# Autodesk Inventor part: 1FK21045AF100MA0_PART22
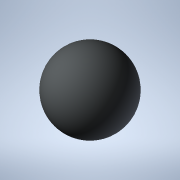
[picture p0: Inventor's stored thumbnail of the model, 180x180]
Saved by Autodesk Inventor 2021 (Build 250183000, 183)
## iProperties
Created: 2025-04
Part Number: 1FK21045AF100MA0_PART22
Material: Generic
Catalog Web Link: www.3dfindit.com
Description: -Servo synchronous motor
Document SubType Name: Modeling
Designer: psAdmin
Mass: 0.137258 g
Surface Area: 1.2868 cm^2
Volume: 0.137258 cm^3
Density: 1 g/cm^3
Appearance: PSOLRGB-212-217-219
Category: PARTsolutions
Title: 1FK21045AF100MA0_PART22
Author: Cadenas PARTsolutions
Comments: Servo synchronous motor
Sending System: PARTsolutions
Preprocessor: ST-DEVELOPER v19.3
PSOL_IDENT_0: {$CADENAS_DATA/23d-libs/siemens_ag/_cat_/52/6b/1fk21045af100ma0.prj},216 {VTYP=3D},{NB=1FK21045AF100
PSOL_IDENT_1: MA0_PART22},{LINA=1FK21045AF100MA0_PART22},{NN=1FK21045AF100MA0_PART22},{NOPRJ=TRUE},{DATE=19.08.202
PSOL_IDENT_2: 5 14:00:38},{GEOMDATE=30.07.2025 02:01:45},{VERSION=},{LINEID=10},{WBVAR=},{WBNUMERIC=}  {NB=1FK2104
PSOL_IDENT_3: 5AF100MA0_PART22},{LINA=1FK21045AF100MA0_PART22},{KT=DUMMY},{PREVIEW=../../../_pool_/cb/72/p_d211_xx
PSOL_IDENT_4: _00434j.png},{DESCSHORT=SIMOTICS S-1FK2 HD, SINAMICS S210 3AC 400V-480V, 2.4 Nm, 3000 rpm},{DESCLONG=
PSOL_IDENT_5: SIMOTICS S-1FK2 HD servo motor M0=2.4 Nm; PN = 0.75 kW at nN=3000 rpm (380-480 V); PN = 0.375 kW at
PSOL_IDENT_6: nN=1500 rpm (200-240 V); with holding brake; degree of protection IP64; cylindrical shaft D19x40mm;
PSOL_IDENT_7: absolute encoder 22-bit + 12-bit multiturn (encoder AM22DQC); with OCC interface; plug size M17, rot
PSOL_IDENT_8: atable; SIMOTICS S-1FK2 servomotorfor a wide range of uses in industrial environments. SIMOTICS S‑1F
PSOL_IDENT_9: K2 servomotors are compact synchronous motors with a high dynamic performance that set themselves ap
PSOL_IDENT_10: art as a result of their high power density, degree of protection and overload capability. The motor
PSOL_IDENT_11: s are available in two variants: as High Dynamic variant (highest dynamic performance as a result of
PSOL_IDENT_12: the low intrinsic moment of inertia for applications demanding a high dynamic performance with low
PSOL_IDENT_13: moved masses) - and as Compact variant (precise and stable closed-loop control for medium up to larg
PSOL_IDENT_14: e moved masses as a result of a medium intrinsic moment of inertia). SIMOTICSS‑1FK2 servomotors full
PSOL_IDENT_15: y exploit their strengths in a system with the SINAMICSS210 frequency converter and simple connectio
PSOL_IDENT_16: n using the one cable connection (OCC). Advantages include the short control and positioning times,
PSOL_IDENT_17: fast and precise correction of disturbing quantities as well as stable control with a high dynamic p
PSOL_IDENT_18: erformance. The servo motors can be configured to address a wide range of requirements. For example
PSOL_IDENT_19: with and without holding brake, IP64 or IP65 degree of protection, singleturn or multiturn absolute
PSOL_IDENT_20: encoders - to name just a few. Further, the servomotors are available in different shaft heights ext
PSOL_IDENT_21: ending from 20 to 100. A shaft sealing ring is available to achieve an IP65 degree of protection and
PSOL_IDENT_22: for subsequent mounting at the motor or as spare part. SIMOTICS - the optimum motor for each and ev
PSOL_IDENT_23: ery motion control application.},{INTNO=804766906411},{SUPPLIERALTNO=1FK2104-5AF10-0MA0},{MANUID=1FK
PSOL_IDENT_24: 21045AF100MA0},{MANUNAME=Siemens},{MANUTYPEDESC=Synchronous motor 1FK2-HD 2.4 NM},{AAU732=SIMOTICS},
PSOL_IDENT_25: {AAO057=S-1FK2},{AAU734=SIMOTICS S-1FK2 HD servo motor M0=2.4 Nm; PN = 0.75 kW at nN=3000 rpm (380-4
PSOL_IDENT_26: 80 V); PN = 0.375 kW at nN=1500 rpm (200-240 V); with holding brake; degree of protection IP64; cyli
PSOL_IDENT_27: ndrical shaft D19x40mm; absolute encoder 22-bit + 12-bit multiturn (encoder AM22DQC); with OCC inter
PSOL_IDENT_28: face; plug size M17, rotatable;},{AAW338=Synchronous motor 1FK2-HD 2.4 NM},{AAO742=SIMOTICS},{AAO663=
PSOL_IDENT_29: 4042948693070},{NOCUPEROU=1},{PRICEQUANTITY=1},{QUANTITYMIN=1},{QUANTITYINT=1},{CTN=85015100},{COO=D
PSOL_IDENT_30: E},{AAO676=1FK2104-5AF10-0MA0},{AAO677=Siemens AG},{ORDERUNIT=C62},{CONTENTUNIT=C62}
NB: 1FK21045AF100MA0_PART22
NT: Servo synchronous motor
NBSYN: $MANUID._PART22
LINA: 1FK21045AF100MA0_PART22
CATALOG: SIEMENS
PREVIEW: ../../../_pool_/cb/72/p_d211_xx_00434j.png
DESCSHORT: SIMOTICS S-1FK2 HD, SINAMICS S210 3AC 400V-480V, 2.4 Nm, 3000 rpm
DESCLONG: SIMOTICS S-1FK2 HD servo motor M0=2.4 Nm; PN = 0.75 kW at nN=3000 rpm (380-480 V); PN = 0.375 kW at nN=1500 rpm (200-240 V); with holding brake; degree of prote
INTNO: 804766906411
SUPPLIERALTNO: 1FK2104-5AF10-0MA0
MANUID: 1FK21045AF100MA0
MANUNAME: Siemens
MANUTYPEDESC: Synchronous motor 1FK2-HD 2.4 NM
AAU732: SIMOTICS
AAO057: S-1FK2
AAU734: SIMOTICS S-1FK2 HD servo motor M0=2.4 Nm; PN = 0.75 kW at nN=3000 rpm (380-480 V); PN = 0.375 kW at nN=1500 rpm (200-240 V); with holding brake; degree of prote
AAW338: Synchronous motor 1FK2-HD 2.4 NM
AAO742: SIMOTICS
AAO663: 4042948693070.0
NOCUPEROU: 1
PRICEQUANTITY: 1
QUANTITYMIN: 1
QUANTITYINT: 1
CTN: 85015100
COO: DE
ARTICLENO: 1FK21045AF100MA0_PART22
BOMINFO: 1FK21045AF100MA0_PART22
CREATOR: CADENAS GmbH
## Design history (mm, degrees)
feature "2025_04_17_15_34_52_0317"
body "Solid1"
